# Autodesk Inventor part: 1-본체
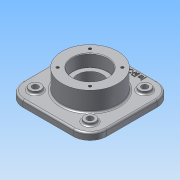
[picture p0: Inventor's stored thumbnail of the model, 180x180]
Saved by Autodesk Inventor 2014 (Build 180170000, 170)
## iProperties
Created: 2015-09
Part Number: 1-본체
Material: 알루미늄 6061
Document SubType Name: Modeling
Designer: study
Density: 2.71 g/cm^3
Appearance: 알루미늄 - 평지
Mass: 1464.68 g
Surface Area: 800.934 cm^2
Volume: 540.471 cm^3
Author: study
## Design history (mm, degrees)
sketch "스케치1"
  geometry: L1 (75, -75)-(-75, -75); L2 (-75, -75)-(-75, 75); L3 (-75, 75)-(75, 75); L4 (75, 75)-(75, -75); L5 (75, -75)-(-75, 75); L6 (-75, -75)-(75, 75); 1 further point
  constraints: 12 end point, 2 midpoint, 2 parallel, 1 horizontal, 1 perpendicular
  dimensions: "d0" = 150 distance of L2.end L3.end; "d1" = 150 distance of L3.end L1.start
extrude "돌출1" new body sketch "스케치1" distance "d2" = 12; taper "d3" = 0 deg
node "작업 평면1"
sketch "스케치2"
  geometry: C1 r 50 at (0, 0); 1 further point
  constraints: 1 centre point, 1 coincident
  dimensions: "d5" = 100 diameter of C1
extrude "돌출2" join sketch "스케치2" distance "d6" = 70; taper "d7" = 0 deg
hole "구멍1" diameter "d10" = 45; stored, may be unused: countersink angle "d14" = 90 deg, drill point angle "d16" = 118 deg; dims "d8" = 10, "d9" = 10, "d11" = 6, "d12" = 62, "d13" = 22, "d15" = 8
hole "구멍2" diameter "d19" = 45; stored, may be unused: countersink angle "d23" = 90 deg, drill point angle "d25" = 118 deg; dims "d17" = 10, "d18" = 10, "d20" = 6, "d21" = 62, "d22" = 22, "d24" = 8
fillet "모깎기1" dims "d26" = 30
sketch "스케치3"
  geometry: C1 r 50 at (0, 0) reference; C2 r 10 at (-49, 49); C3 r 10 at (49, 49); C4 r 10 at (-49, -49); C5 r 10 at (49, -49)
  constraints: 4 centre point, 3 equal radius
  dimensions: "d27" = 20 diameter of C2; "d28" = 49 horizontal distance of C2.centre C1.centre; "d29" = 49 horizontal distance of C2.centre C1.centre; "d30" = 49 horizontal distance of C3.centre C1.centre; "d31" = 49 horizontal distance of C3.centre C1.centre; "d32" = 49 horizontal distance of C1.centre C4.centre; "d33" = 49 horizontal distance of C1.centre C4.centre; "d34" = 49 horizontal distance of C5.centre C1.centre; "d35" = 49 horizontal distance of C5.centre C1.centre
extrude "돌출3" join sketch "스케치3" distance "d36" = 5; taper "d37" = 0 deg
hole "구멍3" diameter "d40" = 11; stored, may be unused: countersink angle "d44" = 90 deg, drill point angle "d46" = 118 deg; dims "d38" = 10, "d39" = 10, "d41" = 6, "d42" = 62, "d43" = 22, "d45" = 8
hole "구멍4" diameter "d49" = 11; stored, may be unused: countersink angle "d53" = 90 deg, drill point angle "d55" = 118 deg; dims "d47" = 10, "d48" = 10, "d50" = 6, "d51" = 62, "d52" = 22, "d54" = 8
hole "구멍5" diameter "d58" = 11; stored, may be unused: countersink angle "d62" = 90 deg, drill point angle "d64" = 118 deg; dims "d56" = 10, "d57" = 10, "d59" = 6, "d60" = 62, "d61" = 22, "d63" = 8
hole "구멍6" diameter "d67" = 11; stored, may be unused: countersink angle "d71" = 90 deg, drill point angle "d73" = 118 deg; dims "d65" = 10, "d66" = 10, "d68" = 6, "d69" = 62, "d70" = 22, "d72" = 8
sketch "스케치4" dims "d35" = 49
  geometry: L1 (28.991, -28.991)-(-28.991, -28.991); L2 (-28.991, -28.991)-(-28.991, 28.991); L3 (-28.991, 28.991)-(28.991, 28.991); L4 (28.991, 28.991)-(28.991, -28.991); L5 (28.991, -28.991)-(-28.991, 28.991); L6 (-28.991, -28.991)-(28.991, 28.991); C1 r 50 at (0, 0) reference; 4 further points
  constraints: 12 end point, 4 coincident, 2 midpoint, 2 parallel, 2 perpendicular, 1 horizontal
  dimensions: "d74" = 82 distance of L1.start L2.end
hole "구멍7" sketch "스케치4" at (-28.991, 28.991), (28.991, 28.991), (28.991, -28.991), (-28.991, -28.991) diameter "d75" = 4.917; stored, may be unused: countersink angle "d79" = 90 deg, drill point angle "d81" = 118 deg; dims "d35" = 49, "d76" = 10, "d77" = 62, "d78" = 22, "d80" = 13
node "작업 평면2"
sketch "스케치5"
  geometry: C1 r 50 at (0, 0) reference; 1 further point
  constraints: 1 vertical alignment, 1 other
  dimensions: "d82" = 65 distance of point (0, 65) C1.centre
feature "엠보싱1" sketch "스케치5" dims "d0" = 150, "d1" = 150, "d26" = 30, "d83" = 1, "d84" = 0
fillet "모깎기2" dims "d85" = 0.3
chamfer "모따기1" distance "d86" = 1; stored, may be unused: second distance "d87" = 2, angle "d88" = 45 deg
fillet "모깎기3" dims "d89" = 3
node "솔리드1"
mirror "대칭1"
other parameters: "d4" = 23
